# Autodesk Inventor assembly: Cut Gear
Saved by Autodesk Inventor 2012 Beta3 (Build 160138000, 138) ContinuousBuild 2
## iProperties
Created: 2011-01
Part Number: Cut Gear
Document SubType Name: Assembly
Designer: Beta-8540w
Categories: <?xml version="1.0" encoding="UTF-16"?> <MemberInstance><Categories><FamilyTemplate/><ParamToTemplateMap><ParamToTemplate><ParamToTemplate CategoryParameter="//
ClientObjectVersion: 1
Author: Beta-8540w
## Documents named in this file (1)
- C:\Inventor 2012 Essentials\Assemblies\Chapter 8\Design Accelerators\Cut Gear c08-01.iam
